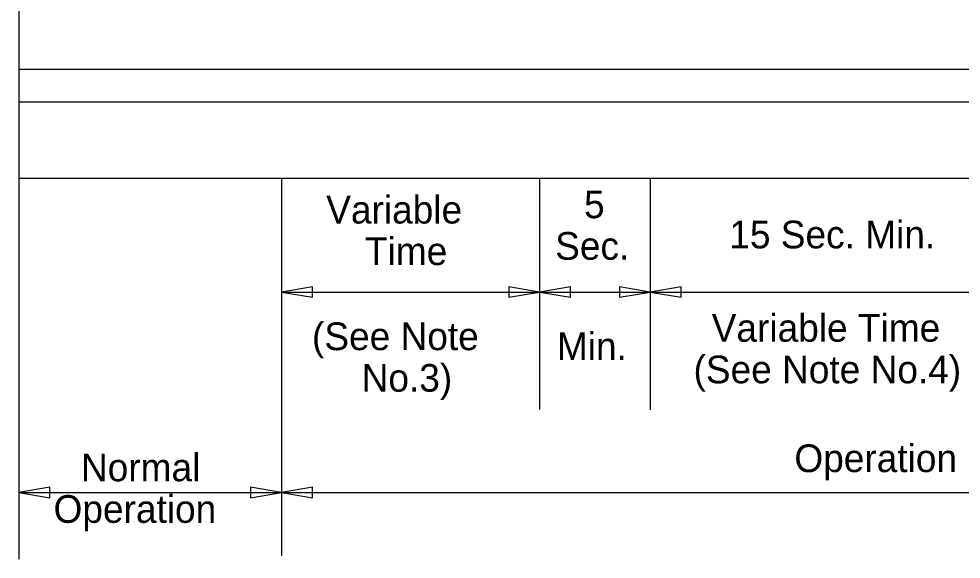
# Model space of a CAD drawing. Extents: x 10000 to 10825, y 10000 to 10530.
# Drawn here: x 10490.2 to 10609.2, y 10048.7 to 10117 of the extents above; entities that cross this region are included whole.
import ezdxf

# ---------------------------------------------------------------- set-up
doc = ezdxf.new("R2010")
doc.units = 0
for name, color, linetype in [('Default', 7, 'Continuous'), ('Dimension', 7, 'Continuous'), ('TextStructures', 7, 'Continuous')]:
    doc.layers.add(name, color=color, linetype=linetype)

msp = doc.modelspace()

# ---------------------------------------------------------------- linework, layer by layer
at = {"layer": 'Default'}
for p, q in [((10490.19, 10185.22), (10490.19, 10048.68)), ((10490.19, 10110.58), (10784.11, 10110.58)), ((10490.19, 10096.84), (10784.11, 10096.84)), ((10523.38, 10096.84), (10523.38, 10049.12)), ((10555.97, 10096.84), (10555.97, 10067.57)), ((10569.96, 10096.79), (10569.96, 10067.53)), ((10523.38, 10082.43), (10555.97, 10082.43)), ((10555.97, 10082.43), (10569.96, 10082.43)), ((10569.96, 10082.43), (10621.07, 10082.43)), ((10490.19, 10057.09), (10523.38, 10057.09)), ((10523.38, 10057.09), (10748.08, 10057.09))]:
    msp.add_line(p, q, dxfattribs=at)
at = {"layer": 'Dimension'}
for points in [[(10523.38, 10082.43), (10527.28, 10081.77), (10527.28, 10083.1)], [(10555.97, 10082.43), (10552.07, 10083.1), (10552.07, 10081.77)], [(10555.97, 10082.43), (10559.88, 10081.77), (10559.88, 10083.1)], [(10569.96, 10082.43), (10566.05, 10083.1), (10566.05, 10081.77)], [(10569.96, 10082.43), (10573.86, 10081.77), (10573.86, 10083.1)], [(10490.19, 10057.09), (10494.09, 10056.43), (10494.09, 10057.76)], [(10523.38, 10057.09), (10519.47, 10057.76), (10519.47, 10056.43)], [(10523.38, 10057.09), (10527.28, 10056.43), (10527.28, 10057.76)]]:
    msp.add_lwpolyline(points, close=True, dxfattribs=at)
at = {"layer": 'TextStructures'}
msp.add_line((10490.19, 10106.45), (10784.11, 10106.45), dxfattribs=at)

# ---------------------------------------------------------------- texts
at = {"layer": 'Default'}
for s, p in [(' Variable Time', (10576.42, 10076.15)), ('(See Note No.4)', (10575.42, 10070.9))]:
    msp.add_text(s, height=3.5, dxfattribs=at).set_placement(p)
at = {"layer": 'TextStructures'}
for s, p in [(' 5', (10560.29, 10091.76)), ('Variable', (10529.02, 10091.09)), ('15 Sec. Min.', (10579.94, 10087.95)), (' Time', (10532.61, 10085.84)), ('Sec.', (10557.94, 10086.51)), ('(See Note', (10527.22, 10075.09)), ('Min.', (10558.16, 10073.83)), (' No.3)', (10532.19, 10069.84)), ('Operation During Bridge Preemption', (10588.16, 10059.68))]:
    msp.add_text(s, height=3.5, dxfattribs=at).set_placement(p)
for s, p in [(' Normal', (10496.73, 10058.52)), ('Operation', (10494.57, 10053.27))]:
    msp.add_text(s, height=3.5, rotation=0.0007, dxfattribs=at).set_placement(p)

doc.saveas('drawing.dxf')
